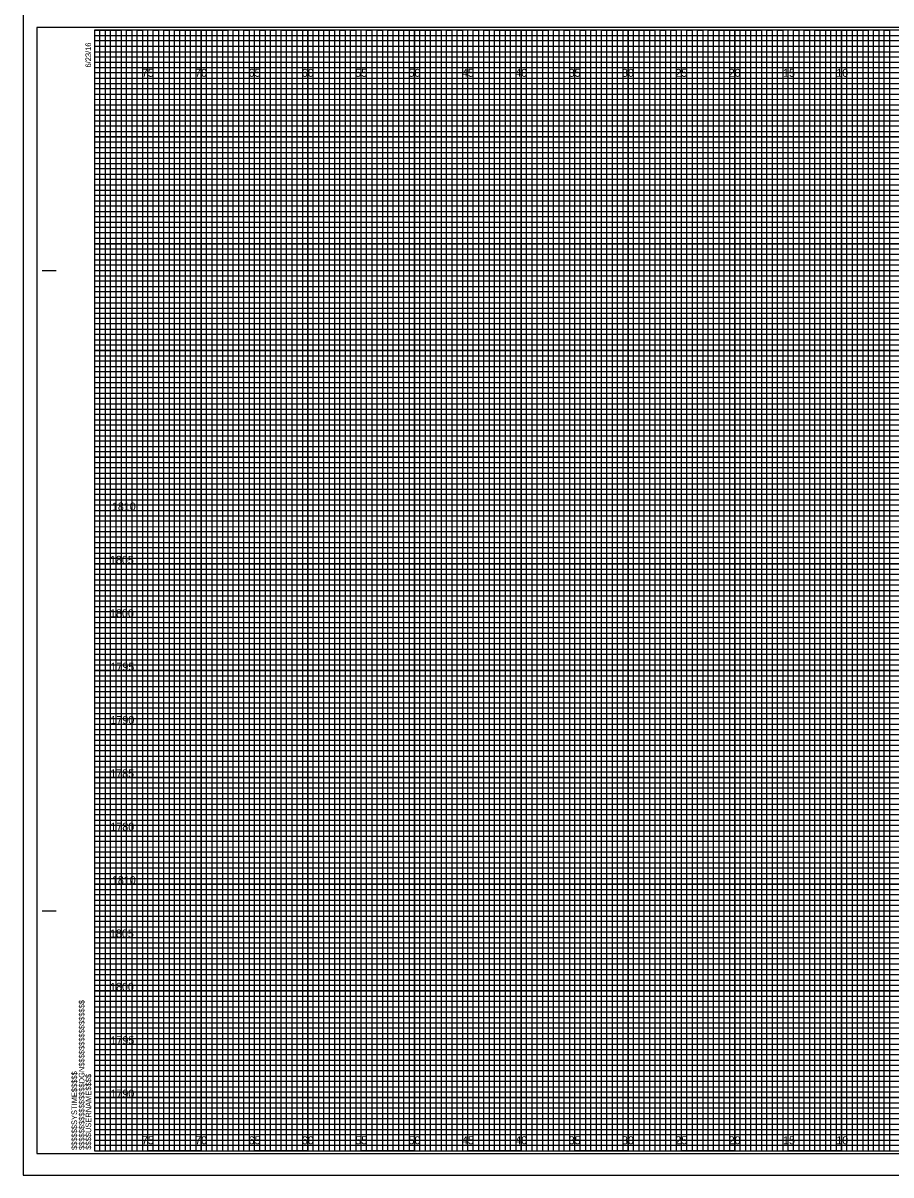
# Model space of a CAD drawing. Extents: x -7 to 392, y -2 to 440.
# Drawn here: x -6.6 to 74.8, y 114.6 to 222.5 of the extents above; entities that cross this region are included whole.
import ezdxf

# ---------------------------------------------------------------- set-up
doc = ezdxf.new("R2010")
doc.units = 0
for name, color, linetype in [('Prop Grid Mask', 7, 'Continuous'), ('Prop XS Elevation Labels', 7, 'Continuous'), ('Sheet Cross Section CELL', 7, 'Continuous'), ('Sheet Cross Section Grid Major CELL', 7, 'Continuous'), ('Sheet Cross Section Grid Middle CELL', 7, 'Continuous'), ('Sheet Cross Section Grid Minor 1 CELL', 7, 'Continuous'), ('Sheet Cross Section Grid Minor 2 CELL', 7, 'Continuous'), ('Sheet Cutting Line CELL', 7, 'Continuous'), ('Sheet DOT Grid CELL', 7, 'Continuous'), ('Sheet Plot Border Inside CELL', 7, 'Continuous'), ('Sheet Plot Border Outside CELL', 7, 'Continuous')]:
    doc.layers.add(name, color=color, linetype=linetype)

msp = doc.modelspace()

# ---------------------------------------------------------------- linework, layer by layer
at = {"layer": 'Sheet Cross Section CELL'}
for p, q in [((-4.77, 199.38), (-3.52, 199.38)), ((-4.72, 199.38), (-3.47, 199.38)), ((-4.77, 139.38), (-3.52, 139.38)), ((-4.72, 139.38), (-3.47, 139.38)), ((0.13, 116.88), (0.13, 116.88)), ((0.13, 116.88), (0.13, 116.88)), ((0.13, 116.88), (0.13, 116.88)), ((0.13, 116.88), (0.13, 116.88)), ((0.13, 116.88), (0.13, 116.88)), ((0.13, 116.88), (0.13, 116.88)), ((0.13, 116.88), (0.13, 116.88))]:
    msp.add_line(p, q, dxfattribs=at)
msp.add_lwpolyline([(160.13, 221.88), (0.13, 221.88), (0.13, 116.88), (160.13, 116.88)], close=True, dxfattribs=at)
at = {"layer": 'Sheet Cross Section Grid Major CELL'}
for p, q in [((5.13, 221.88), (0.13, 221.88)), ((5.13, 116.88), (5.13, 221.88)), ((15.13, 221.88), (10.13, 221.88)), ((10.13, 221.88), (10.13, 116.88)), ((15.13, 116.88), (15.13, 221.88)), ((25.13, 221.88), (20.13, 221.88)), ((20.13, 221.88), (20.13, 116.88)), ((25.13, 116.88), (25.13, 221.88)), ((35.13, 221.88), (30.13, 221.88)), ((30.13, 221.88), (30.13, 116.88)), ((35.13, 116.88), (35.13, 221.88)), ((45.13, 221.88), (40.13, 221.88)), ((40.13, 221.88), (40.13, 116.88)), ((45.13, 116.88), (45.13, 221.88)), ((55.13, 221.88), (50.13, 221.88)), ((50.13, 221.88), (50.13, 116.88)), ((55.13, 116.88), (55.13, 221.88)), ((65.13, 221.88), (60.13, 221.88)), ((60.13, 221.88), (60.13, 116.88)), ((65.13, 116.88), (65.13, 221.88)), ((75.13, 221.88), (70.13, 221.88)), ((70.13, 221.88), (70.13, 116.88)), ((10.13, 116.88), (5.13, 116.88)), ((20.13, 116.88), (15.13, 116.88)), ((30.13, 116.88), (25.13, 116.88)), ((40.13, 116.88), (35.13, 116.88)), ((50.13, 116.88), (45.13, 116.88)), ((60.13, 116.88), (55.13, 116.88)), ((70.13, 116.88), (65.13, 116.88))]:
    msp.add_line(p, q, dxfattribs=at)
for points in [[(0.13, 216.88), (160.13, 216.88), (160.13, 211.88), (0.13, 211.88)], [(0.13, 206.88), (160.13, 206.88), (160.13, 201.88), (0.13, 201.88)], [(0.13, 196.88), (160.13, 196.88), (160.13, 191.88), (0.13, 191.88)], [(0.13, 186.88), (160.13, 186.88), (160.13, 181.88), (0.13, 181.88)], [(0.13, 176.88), (160.13, 176.88), (160.13, 171.88), (0.13, 171.88)], [(0.13, 166.88), (160.13, 166.88), (160.13, 161.88), (0.13, 161.88)], [(0.13, 156.88), (160.13, 156.88), (160.13, 151.88), (0.13, 151.88)], [(0.13, 146.88), (160.13, 146.88), (160.13, 141.88), (0.13, 141.88)], [(0.13, 136.88), (160.13, 136.88), (160.13, 131.88), (0.13, 131.88)], [(0.13, 126.88), (160.13, 126.88), (160.13, 121.88), (0.13, 121.88)]]:
    msp.add_lwpolyline(points, dxfattribs=at)
at = {"layer": 'Sheet Cross Section Grid Middle CELL'}
for points in [[(0.13, 221.88), (2.63, 221.88), (2.63, 116.88), (7.63, 116.88), (7.63, 221.88), (12.63, 221.88), (12.63, 116.88), (17.63, 116.88), (17.63, 221.88), (22.63, 221.88), (22.63, 116.88), (27.63, 116.88), (27.63, 221.88), (32.63, 221.88), (32.63, 116.88), (37.63, 116.88), (37.63, 221.88), (42.63, 221.88), (42.63, 116.88), (47.63, 116.88), (47.63, 221.88), (52.63, 221.88), (52.63, 116.88), (57.63, 116.88), (57.63, 221.88), (62.63, 221.88), (62.63, 116.88), (67.63, 116.88), (67.63, 221.88), (72.63, 221.88), (72.63, 116.88), (77.63, 116.88)], [(0.13, 219.38), (137.63, 219.38)], [(0.13, 209.38), (160.13, 209.38), (160.13, 214.38), (0.13, 214.38)], [(0.13, 199.38), (160.13, 199.38), (160.13, 204.38), (0.13, 204.38)], [(0.13, 189.38), (160.13, 189.38), (160.13, 194.38), (0.13, 194.38)], [(0.13, 179.38), (160.13, 179.38), (160.13, 184.38), (0.13, 184.38)], [(0.13, 169.38), (160.13, 169.38), (160.13, 174.38), (0.13, 174.38)], [(0.13, 159.38), (160.13, 159.38), (160.13, 164.38), (0.13, 164.38)], [(0.13, 149.38), (160.13, 149.38), (160.13, 154.38), (0.13, 154.38)], [(0.13, 139.38), (160.13, 139.38), (160.13, 144.38), (0.13, 144.38)], [(0.13, 129.38), (160.13, 129.38), (160.13, 134.38), (0.13, 134.38)], [(0.13, 119.38), (160.13, 119.38), (160.13, 124.38), (0.13, 124.38)]]:
    msp.add_lwpolyline(points, dxfattribs=at)
at = {"layer": 'Sheet Cross Section Grid Minor 1 CELL'}
for p, q in [((0.13, 221.38), (130.13, 221.38)), ((130.13, 220.87), (0.13, 220.87)), ((0.13, 220.87), (0.13, 220.38)), ((0.13, 220.38), (130.13, 220.38)), ((130.13, 219.83), (0.13, 219.83)), ((0.13, 219.83), (0.13, 218.88)), ((0.13, 218.88), (160.13, 218.88))]:
    msp.add_line(p, q, dxfattribs=at)
for points in [[(0.13, 218.38), (135.13, 218.38), (160.13, 218.38), (160.13, 217.88), (0.13, 217.88)], [(0.13, 217.38), (160.13, 217.38), (160.13, 216.38), (0.13, 216.38)], [(0.13, 215.88), (160.13, 215.88), (160.13, 215.38), (0.13, 215.37)], [(0.13, 214.88), (160.13, 214.88), (160.13, 213.88), (0.13, 213.88)], [(0.13, 213.38), (160.13, 213.38), (160.13, 212.88), (0.13, 212.88)], [(0.13, 212.38), (160.13, 212.38), (160.13, 211.38), (0.13, 211.38)], [(0.13, 210.88), (160.13, 210.88), (160.13, 210.38), (0.13, 210.38)], [(0.13, 209.88), (160.13, 209.88), (160.13, 208.88), (0.13, 208.88)], [(0.13, 208.38), (160.13, 208.38), (160.13, 207.88), (0.13, 207.88)], [(0.13, 207.38), (160.13, 207.38), (160.13, 206.38), (0.13, 206.38)], [(0.13, 205.88), (160.13, 205.88), (160.13, 205.38), (0.13, 205.38)], [(0.13, 204.88), (160.13, 204.88), (160.13, 203.86), (160.13, 203.38), (160.13, 202.88), (0.13, 202.88)], [(0.13, 203.88), (160.13, 203.88), (160.13, 203.38), (0.13, 203.38)], [(0.13, 202.38), (160.13, 202.38), (160.13, 201.38), (0.13, 201.4)], [(0.13, 201.4), (160.13, 201.38), (160.13, 200.88), (0.13, 200.88)], [(0.13, 200.38), (160.13, 200.38), (160.13, 199.88), (0.13, 199.88)], [(0.13, 198.88), (160.13, 198.88), (160.13, 198.38), (0.13, 198.38)], [(0.13, 197.88), (160.13, 197.88), (160.13, 197.38), (0.13, 197.38)], [(0.1, 196.33), (160.13, 196.33), (160.13, 195.82), (0.1, 195.82)], [(0.13, 195.38), (160.13, 195.38), (160.13, 194.88), (0.13, 194.88)], [(0.13, 193.88), (160.13, 193.88), (160.13, 193.38), (0.13, 193.38)], [(0.13, 192.88), (160.13, 192.88), (160.13, 192.38), (0.13, 192.38)], [(0.13, 191.38), (160.13, 191.38), (160.13, 190.88), (0.13, 190.88)], [(0.13, 190.38), (160.13, 190.38), (160.13, 189.88), (0.13, 189.88)], [(0.13, 188.88), (160.13, 188.88), (160.13, 188.38), (0.13, 188.38)], [(0.13, 187.88), (160.13, 187.88), (160.13, 187.38), (0.13, 187.38)], [(0.13, 186.38), (160.13, 186.38), (160.13, 185.87), (0.13, 185.88)], [(0.13, 185.38), (160.13, 185.38), (160.13, 184.88), (0.13, 184.88)], [(0.13, 183.88), (160.13, 183.88), (160.13, 183.38), (0.13, 183.38)], [(0.13, 182.88), (160.13, 182.88), (160.13, 182.38), (0.13, 182.38)], [(0.13, 181.38), (160.13, 181.38), (160.13, 180.88), (0.13, 180.88)], [(0.13, 180.38), (160.13, 180.38), (160.13, 179.88), (0.13, 179.88)], [(0.13, 178.88), (160.13, 178.88), (160.13, 178.38), (0.13, 178.38)], [(0.13, 177.88), (160.13, 177.88), (160.13, 177.38), (0.13, 177.38)], [(0.13, 176.38), (160.13, 176.38), (160.13, 175.88), (0.13, 175.88)], [(0.13, 175.38), (160.17, 175.34), (160.13, 174.88), (0.13, 174.88)], [(0.13, 173.88), (160.13, 173.88), (160.13, 173.38), (0.13, 173.38)], [(0.13, 172.88), (160.13, 172.88), (160.13, 172.38), (0.13, 172.38)], [(0.13, 171.38), (160.13, 171.38), (160.13, 170.88), (0.13, 170.88)], [(0.13, 170.38), (160.13, 170.38), (160.13, 169.88), (0.13, 169.88)], [(0.13, 168.88), (160.13, 168.88), (160.13, 168.38), (0.13, 168.38)], [(0.13, 167.88), (160.13, 167.88), (160.13, 167.38), (0.13, 167.38)], [(0.13, 166.38), (160.13, 166.38), (160.13, 165.88), (0.13, 165.88)], [(0.13, 165.38), (160.13, 165.38), (160.13, 164.88), (0.13, 164.88)], [(0.13, 163.88), (160.13, 163.88), (160.13, 163.38), (0.13, 163.38)], [(0.13, 162.88), (160.13, 162.88), (160.13, 162.38), (0.13, 162.38)], [(0.13, 161.38), (160.13, 161.38), (160.13, 160.88), (0.13, 160.88)], [(0.13, 160.38), (160.13, 160.38), (160.13, 159.88), (0.13, 159.88)], [(0.13, 158.88), (160.13, 158.88), (160.13, 158.38), (0.13, 158.38)], [(0.13, 157.88), (160.13, 157.88), (160.13, 157.38), (0.13, 157.38)], [(0.13, 156.38), (160.13, 156.38), (160.13, 155.87), (0.13, 155.88)], [(0.13, 155.38), (160.13, 155.38), (160.13, 154.88), (0.13, 154.88)], [(0.13, 153.88), (160.13, 153.88), (160.13, 153.38), (0.13, 153.38)], [(0.13, 152.88), (160.13, 152.88), (160.13, 152.38), (0.13, 152.38)], [(0.13, 151.38), (160.13, 151.38), (160.13, 150.88), (0.13, 150.88)], [(0.13, 150.38), (160.13, 150.38), (160.13, 149.88), (0.13, 149.88)], [(0.13, 148.88), (160.13, 148.88), (160.13, 148.38), (0.13, 148.38)], [(0.13, 147.88), (160.13, 147.88), (160.13, 147.38), (0.13, 147.38)], [(0.13, 146.38), (160.13, 146.38), (160.13, 145.88), (0.13, 145.88)], [(0.13, 145.38), (160.17, 145.34), (160.13, 144.88), (0.13, 144.88)], [(0.13, 143.88), (160.13, 143.88), (160.13, 143.38), (0.13, 143.38)], [(0.13, 142.88), (160.13, 142.88), (160.13, 142.38), (0.13, 142.38)], [(0.13, 141.38), (160.13, 141.38), (160.13, 140.88), (0.13, 140.88)], [(0.13, 140.38), (160.13, 140.38), (160.13, 139.88), (0.13, 139.88)], [(0.13, 138.88), (160.13, 138.88), (160.13, 138.38), (0.13, 138.38)], [(0.13, 137.88), (160.13, 137.88), (160.13, 137.38), (0.13, 137.38)], [(0.13, 136.38), (160.13, 136.38), (160.13, 135.88), (0.13, 135.88)], [(0.13, 135.38), (160.13, 135.38), (160.13, 134.88), (0.13, 134.88)], [(0.13, 133.88), (160.13, 133.88), (160.13, 133.38), (0.13, 133.38)], [(0.13, 132.88), (160.13, 132.88), (160.13, 132.38), (0.13, 132.38)], [(0.13, 131.38), (160.13, 131.38), (160.13, 130.88), (0.13, 130.88)], [(0.13, 130.38), (160.13, 130.38), (160.13, 129.88), (0.13, 129.88)], [(0.13, 128.88), (160.13, 128.88), (160.13, 128.38), (0.13, 128.38)], [(0.13, 127.88), (160.13, 127.88), (160.13, 127.38), (0.13, 127.38)], [(0.13, 126.38), (160.13, 126.38), (160.13, 125.88), (0.13, 125.88)], [(0.13, 125.38), (160.13, 125.38), (160.13, 124.88), (0.13, 124.88)], [(0.13, 123.88), (160.13, 123.88), (160.13, 123.38), (0.13, 123.38)], [(0.13, 122.88), (160.13, 122.88), (160.13, 122.38), (0.13, 122.38)], [(0.13, 121.38), (160.13, 121.38), (160.13, 120.88), (0.13, 120.88)], [(0.13, 120.38), (160.13, 120.38), (160.13, 119.88), (0.13, 119.88)], [(0.13, 118.88), (160.13, 118.88), (160.13, 118.38), (0.13, 118.38)], [(0.13, 117.88), (160.13, 117.88), (160.13, 117.38), (0.13, 117.38)]]:
    msp.add_lwpolyline(points, dxfattribs=at)
at = {"layer": 'Sheet Cross Section Grid Minor 2 CELL'}
for points in [[(0.13, 116.88), (0.63, 116.88), (0.63, 221.88), (1.13, 221.88), (1.13, 116.88)], [(1.13, 116.88), (1.63, 116.88), (1.63, 221.88), (2.13, 221.88), (2.13, 116.88)], [(2.63, 116.88), (3.13, 116.88), (3.13, 221.88), (3.63, 221.88), (3.63, 116.88)], [(3.63, 116.88), (4.13, 116.88), (4.13, 221.88), (4.63, 221.88), (4.63, 116.88)], [(5.13, 116.88), (5.63, 116.88), (5.63, 221.88), (6.13, 221.88), (6.13, 116.88)], [(6.13, 116.88), (6.63, 116.88), (6.63, 221.88), (7.13, 221.88), (7.13, 116.88)], [(7.63, 116.88), (8.13, 116.88), (8.13, 221.88), (8.63, 221.88), (8.63, 116.88)], [(8.63, 116.88), (9.13, 116.88), (9.13, 221.88), (9.63, 221.88), (9.63, 116.88)], [(10.13, 116.88), (10.63, 116.88), (10.63, 221.88), (11.13, 221.88), (11.13, 116.88)], [(11.13, 116.88), (11.63, 116.88), (11.63, 221.88), (12.13, 221.88), (12.13, 116.88)], [(12.63, 116.88), (13.13, 116.88), (13.13, 221.88), (13.63, 221.88), (13.63, 116.88)], [(13.63, 116.88), (14.13, 116.88), (14.13, 221.88), (14.63, 221.88), (14.63, 116.88)], [(15.13, 116.88), (15.63, 116.88), (15.63, 221.88), (16.13, 221.88), (16.13, 116.88)], [(16.13, 116.88), (16.63, 116.88), (16.63, 221.88), (17.13, 221.88), (17.13, 116.88)], [(17.63, 116.88), (18.13, 116.88), (18.13, 221.88), (18.63, 221.88), (18.63, 116.88)], [(18.63, 116.88), (19.13, 116.88), (19.13, 221.88), (19.63, 221.88), (19.63, 116.88)], [(20.13, 116.88), (20.63, 116.88), (20.63, 221.88), (21.13, 221.88), (21.13, 116.88)], [(21.13, 116.88), (21.63, 116.88), (21.63, 221.88), (22.13, 221.88), (22.13, 116.88)], [(22.63, 116.88), (23.13, 116.88), (23.13, 221.88), (23.63, 221.88), (23.63, 116.88)], [(23.63, 116.88), (24.13, 116.88), (24.13, 221.88), (24.63, 221.88), (24.63, 116.88)], [(25.13, 116.88), (25.63, 116.88), (25.63, 221.88), (26.13, 221.88), (26.13, 116.88)], [(26.13, 116.88), (26.63, 116.88), (26.63, 221.88), (27.13, 221.88), (27.13, 116.88)], [(27.63, 116.88), (28.13, 116.88), (28.13, 221.88), (28.63, 221.88), (28.63, 116.88)], [(28.63, 116.88), (29.13, 116.88), (29.13, 221.88), (29.63, 221.88), (29.63, 116.88)], [(30.13, 116.88), (30.63, 116.88), (30.63, 221.88), (31.13, 221.88), (31.13, 116.88)], [(31.13, 116.88), (31.63, 116.88), (31.63, 221.88), (32.13, 221.88), (32.13, 116.88)], [(32.63, 116.88), (33.13, 116.88), (33.13, 221.88), (33.63, 221.88), (33.63, 116.88)], [(33.63, 116.88), (34.13, 116.88), (34.13, 221.88), (34.63, 221.88), (34.63, 116.88)], [(35.13, 116.88), (35.63, 116.88), (35.63, 221.88), (36.13, 221.88), (36.13, 116.88)], [(36.13, 116.88), (36.63, 116.88), (36.63, 221.88), (37.13, 221.88), (37.13, 116.88)], [(37.63, 116.88), (38.13, 116.88), (38.13, 221.88), (38.63, 221.88), (38.63, 116.88)], [(38.63, 116.88), (39.13, 116.88), (39.13, 221.88), (39.63, 221.88), (39.63, 116.88)], [(40.13, 116.88), (40.63, 116.88), (40.63, 221.88), (41.13, 221.88), (41.13, 116.88)], [(41.13, 116.88), (41.63, 116.88), (41.63, 221.88), (42.13, 221.88), (42.13, 116.88)], [(42.63, 116.88), (43.13, 116.88), (43.13, 221.88), (43.63, 221.88), (43.63, 116.88)], [(43.63, 116.88), (44.13, 116.88), (44.13, 221.88), (44.63, 221.88), (44.63, 116.88)], [(45.13, 116.88), (45.63, 116.88), (45.63, 221.88), (46.13, 221.88), (46.13, 116.88)], [(46.13, 116.88), (46.63, 116.88), (46.63, 221.88), (47.13, 221.88), (47.13, 116.88)], [(47.63, 116.88), (48.13, 116.88), (48.13, 221.88), (48.63, 221.88), (48.63, 116.88)], [(48.63, 116.88), (49.13, 116.88), (49.13, 221.88), (49.63, 221.88), (49.63, 116.88)], [(50.13, 116.88), (50.63, 116.88), (50.63, 221.88), (51.13, 221.88), (51.13, 116.88)], [(51.13, 116.88), (51.63, 116.88), (51.63, 221.88), (52.13, 221.88), (52.13, 116.88)], [(52.63, 116.88), (53.13, 116.88), (53.13, 221.88), (53.63, 221.88), (53.63, 116.88)], [(53.63, 116.88), (54.13, 116.88), (54.13, 221.88), (54.63, 221.88), (54.63, 116.88)], [(55.13, 116.88), (55.63, 116.88), (55.63, 221.88), (56.13, 221.88), (56.13, 116.88)], [(56.13, 116.88), (56.63, 116.88), (56.63, 221.88), (57.13, 221.88), (57.13, 116.88)], [(57.63, 116.88), (58.13, 116.88), (58.13, 221.88), (58.63, 221.88), (58.63, 116.88)], [(58.63, 116.88), (59.13, 116.88), (59.13, 221.88), (59.63, 221.88), (59.63, 116.88)], [(60.13, 116.88), (60.63, 116.88), (60.63, 221.88), (61.13, 221.88), (61.13, 116.88)], [(61.13, 116.88), (61.63, 116.88), (61.63, 221.88), (62.13, 221.88), (62.13, 116.88)], [(62.63, 116.88), (63.13, 116.88), (63.13, 221.88), (63.63, 221.88), (63.63, 116.88)], [(63.63, 116.88), (64.13, 116.88), (64.13, 221.88), (64.63, 221.88), (64.63, 116.88)], [(65.13, 116.88), (65.63, 116.88), (65.63, 221.88), (66.13, 221.88), (66.13, 116.88)], [(66.13, 116.88), (66.63, 116.88), (66.63, 221.88), (67.13, 221.88), (67.13, 116.88)], [(67.63, 116.88), (68.13, 116.88), (68.13, 221.88), (68.63, 221.88), (68.63, 116.88)], [(68.63, 116.88), (69.13, 116.88), (69.13, 221.88), (69.63, 221.88), (69.63, 116.88)], [(70.13, 116.88), (70.63, 116.88), (70.63, 221.88), (71.13, 221.88), (71.13, 116.88)], [(71.13, 116.88), (71.63, 116.88), (71.63, 221.88), (72.13, 221.88), (72.13, 116.88)], [(72.63, 116.88), (73.13, 116.88), (73.13, 221.88), (73.63, 221.88), (73.63, 116.88)], [(73.63, 116.88), (74.13, 116.88), (74.13, 221.88), (74.63, 221.88), (74.63, 116.88)]]:
    msp.add_lwpolyline(points, dxfattribs=at)
at = {"layer": 'Sheet Cutting Line CELL'}
for p, q in [((-6.57, 224.13), (-6.57, 114.63)), ((-6.57, 114.63), (161.78, 114.63))]:
    msp.add_line(p, q, dxfattribs=at)
at = {"layer": 'Sheet DOT Grid CELL'}
for p, q in [((5.13, 116.88), (5.13, 221.88)), ((10.13, 116.88), (10.13, 221.88)), ((15.13, 116.88), (15.13, 221.88)), ((20.13, 116.88), (20.13, 221.88)), ((25.13, 116.88), (25.13, 221.88)), ((30.13, 116.88), (30.13, 221.88)), ((35.13, 116.88), (35.13, 221.88)), ((40.13, 116.88), (40.13, 221.88)), ((45.13, 116.88), (45.13, 221.88)), ((50.13, 116.88), (50.13, 221.88)), ((55.13, 116.88), (55.13, 221.88)), ((60.13, 116.88), (60.13, 221.88)), ((65.13, 116.88), (65.13, 221.88)), ((70.13, 116.88), (70.13, 221.88)), ((0.13, 216.88), (160.13, 216.88)), ((0.13, 211.88), (160.13, 211.88)), ((0.13, 206.88), (160.13, 206.88)), ((0.13, 201.88), (160.13, 201.88)), ((0.13, 196.88), (160.13, 196.88)), ((0.13, 191.88), (160.13, 191.88)), ((0.13, 186.88), (160.13, 186.88)), ((0.13, 181.88), (160.13, 181.88)), ((0.13, 176.88), (160.13, 176.88)), ((0.13, 171.88), (160.13, 171.88)), ((0.13, 166.88), (160.13, 166.88)), ((0.13, 161.88), (160.13, 161.88)), ((0.13, 156.88), (160.13, 156.88)), ((0.13, 151.88), (160.13, 151.88)), ((0.13, 146.88), (160.13, 146.88)), ((0.13, 141.88), (160.13, 141.88)), ((0.13, 136.88), (160.13, 136.88)), ((0.13, 131.88), (160.13, 131.88)), ((0.13, 126.88), (160.13, 126.88)), ((0.13, 121.88), (160.13, 121.88))]:
    msp.add_line(p, q, dxfattribs=at)
at = {"layer": 'Sheet Plot Border Inside CELL'}
msp.add_lwpolyline([(-5.27, 116.63), (161.33, 116.63), (161.33, 222.13), (-5.27, 222.13)], close=True, dxfattribs=at)
at = {"layer": 'Sheet Plot Border Outside CELL'}
msp.add_lwpolyline([(-6.57, 114.63), (161.78, 114.63), (161.78, 224.13), (-6.57, 224.13)], close=True, dxfattribs=at)

# ---------------------------------------------------------------- texts
at = {"layer": 'Prop Grid Mask'}
for s, p in [('75', (4.57, 217.51)), ('70', (9.56, 217.51)), ('65', (14.57, 217.51)), ('60', (19.56, 217.51)), ('55', (24.57, 217.51)), ('50', (29.56, 217.51)), ('45', (34.57, 217.51)), ('40', (39.56, 217.51)), ('35', (44.57, 217.51)), ('30', (49.56, 217.51)), ('25', (54.57, 217.51)), ('20', (59.56, 217.51)), ('15', (64.66, 217.51)), ('10', (69.65, 217.51)), ('75', (4.57, 117.51)), ('70', (9.56, 117.51)), ('65', (14.57, 117.51)), ('60', (19.56, 117.51)), ('55', (24.57, 117.51)), ('50', (29.56, 117.51)), ('45', (34.57, 117.51)), ('40', (39.56, 117.51)), ('35', (44.57, 117.51)), ('30', (49.56, 117.51)), ('25', (54.57, 117.51)), ('20', (59.56, 117.51)), ('15', (64.66, 117.51)), ('10', (69.65, 117.51))]:
    msp.add_text(s, height=0.75, dxfattribs=at).set_placement(p)
at = {"layer": 'Prop XS Elevation Labels'}
for s, p in [('1810', (1.76, 176.88)), ('1805', (1.58, 171.88)), ('1800', (1.59, 166.88)), ('1795', (1.63, 161.88)), ('1790', (1.63, 156.88)), ('1785', (1.61, 151.88)), ('1780', (1.62, 146.88)), ('1810', (1.76, 141.88)), ('1805', (1.58, 136.88)), ('1800', (1.59, 131.88)), ('1795', (1.63, 126.88)), ('1790', (1.63, 121.88))]:
    msp.add_text(s, height=0.75, dxfattribs=at).set_placement(p)
at = {"layer": 'Sheet Cross Section CELL'}
for s, p in [('6/23/16', (-0.19, 218.38)), ('$$$$$$$$$$$$$$$$DGN$$$$$$$$$$$$$$$$', (-0.81, 116.97)), ('$$$$$$SYSTIME$$$$$', (-1.5, 116.97)), ('$$$$USERNAME$$$$', (-0.18, 117))]:
    msp.add_text(s, height=0.525, rotation=90, dxfattribs=at).set_placement(p)

doc.saveas('drawing.dxf')
